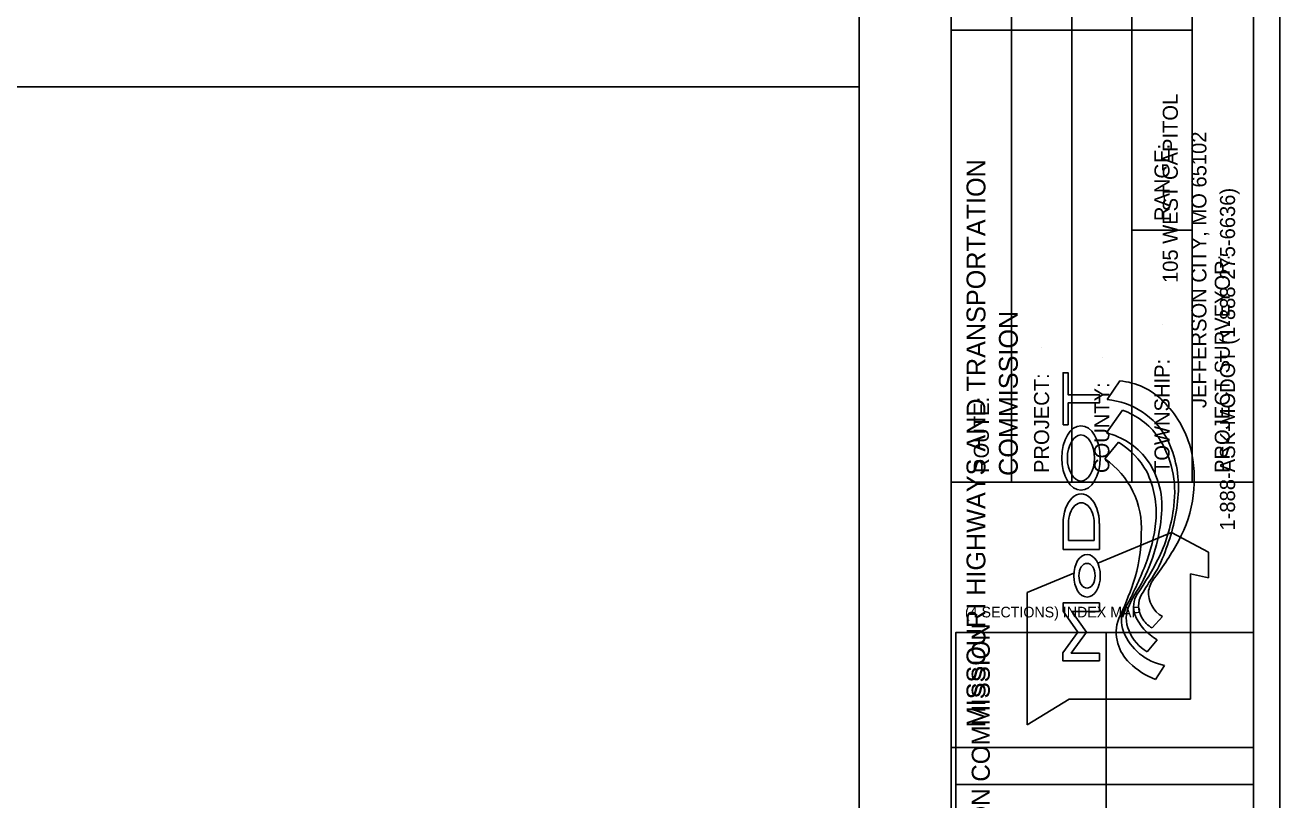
# Model space of a CAD drawing. Extents: x 0 to 31.6, y 0 to 20.8.
# Drawn here: x 23.27 to 31.6, y 5.11 to 10.25 of the extents above; entities that cross this region are included whole.
import ezdxf

# ---------------------------------------------------------------- set-up
doc = ezdxf.new("R2010")
doc.units = 0
for name, color, linetype in [('Border-Border', 7, 'Continuous'), ('Border-Bridge survey map', 7, 'Continuous'), ('Border-Full plan shape', 7, 'Continuous'), ('Border-Full profile shape', 7, 'Continuous'), ('Border-Plan bottom shape', 7, 'Continuous'), ('Border-Plotting block', 7, 'Continuous'), ('Border-Profile bottom shape', 7, 'Continuous'), ('Border-Title block - Final Plans Consultant Manual Seal', 7, 'Continuous'), ('Border-Title block - Final Plans Electronic Seal', 7, 'Continuous'), ('Border-Title block - Location Survey Electronic Seal', 7, 'Continuous'), ('Border-Xsection shape', 7, 'Continuous')]:
    doc.layers.add(name, color=color, linetype=linetype)

msp = doc.modelspace()

# ---------------------------------------------------------------- linework, layer by layer
at = {"layer": 'Border-Border'}
msp.add_line((31.425, 20.5875), (31.425, 0.2125), dxfattribs=at)
at = {"layer": 'Border-Bridge survey map'}
for p, q in [((30.4469, 6.2219), (30.4469, 4.2046)), ((29.4469, 5.2141), (31.4249, 5.2141))]:
    msp.add_line(p, q, dxfattribs=at)
msp.add_lwpolyline([(29.4469, 4.2046), (29.4469, 6.2219), (31.4249, 6.2219)], dxfattribs=at)
at = {"layer": 'Border-Full plan shape'}
msp.add_lwpolyline([(0.8061, 19.9564), (28.8061, 19.9564), (28.8061, 0.8436), (0.8061, 0.8436)], close=True, dxfattribs=at)
at = {"layer": 'Border-Full profile shape'}
msp.add_lwpolyline([(0.8061, 19.9564), (28.8061, 19.9564), (28.8061, 0.8436), (0.8061, 0.8436)], close=True, dxfattribs=at)
at = {"layer": 'Border-Plan bottom shape'}
msp.add_lwpolyline([(0.8061, 10.3253), (28.8061, 10.3253), (28.8061, 0.8436), (0.8061, 0.8436)], close=True, dxfattribs=at)
at = {"layer": 'Border-Plotting block'}
msp.add_lwpolyline([(0, 0), (31.5999, 0), (31.5999, 20.8), (0, 20.8)], close=True, dxfattribs=at)
at = {"layer": 'Border-Profile bottom shape'}
msp.add_lwpolyline([(0.8061, 0.8436), (28.8061, 0.8436), (28.8061, 9.8436), (0.8061, 9.8436)], close=True, dxfattribs=at)
at = {"layer": 'Border-Title block - Final Plans Consultant Manual Seal'}
for p, q in [((29.4171, 20.5875), (29.4171, 0.2125)), ((30.5365, 7.8922), (30.4519, 7.768)), ((30.5541, 7.6979), (30.4483, 7.5468)), ((30.5272, 7.4859), (30.4378, 7.3747)), ((30.16, 6.9464), (30.16, 6.774)), ((30.1963, 6.8334), (30.1963, 6.9464)), ((30.3662, 6.9464), (30.3662, 6.8334)), ((30.4008, 6.774), (30.4008, 6.9464)), ((30.3662, 6.8334), (30.1963, 6.8334)), ((30.8803, 6.8869), (30.3903, 6.6831)), ((31.1267, 6.7566), (30.8803, 6.8869)), ((30.16, 6.774), (30.4008, 6.774)), ((31.1267, 6.5855), (31.1267, 6.7566)), ((30.2315, 6.617), (29.922, 6.4883)), ((31.0071, 5.7793), (31.0071, 6.6109)), ((31.0071, 6.6109), (31.1267, 6.5855)), ((29.922, 6.4883), (29.922, 5.6099)), ((30.7517, 6.2525), (30.821, 6.3285)), ((30.7188, 6.0943), (30.7857, 6.1748)), ((30.7729, 5.9114), (30.8329, 6.0039)), ((29.922, 5.6099), (30.2004, 5.7793)), ((30.2004, 5.7793), (31.0071, 5.7793)), ((29.4171, 5.4599), (31.425, 5.4599))]:
    msp.add_line(p, q, dxfattribs=at)
for points in [[(30.1599, 7.6015), (30.1599, 7.9459), (30.1934, 7.9459), (30.1934, 7.8005), (30.4008, 7.8005), (30.4008, 7.7459), (30.1934, 7.7459), (30.1934, 7.6015)], [(30.4008, 6.0337), (30.1592, 6.0337), (30.1592, 6.0882), (30.2588, 6.2251), (30.16, 6.3638), (30.16, 6.4193), (30.4008, 6.4193), (30.4008, 6.3619), (30.2185, 6.3619), (30.3164, 6.2251), (30.2147, 6.0844), (30.4008, 6.0844)]]:
    msp.add_lwpolyline(points, close=True, dxfattribs=at)
for centre, radius, start, end in [((30.4952, 7.4285), 0.4656, 45.16931, 84.90202), ((30.4076, 7.2631), 0.5069, 28.57249, 84.98895), ((30.3292, 7.2587), 0.7029, 15.82215, 45.3322), ((30.3947, 7.2387), 0.486, 35.48059, 70.84743), ((30.3361, 7.0832), 0.477, 37.82053, 76.39644), ((30.2462, 7.1558), 0.6553, 351.92721, 33.85401), ((30.1918, 7.186), 0.7342, 356.25263, 25.80365), ((30.2447, 7.0264), 0.5393, 29.26655, 58.41911), ((30.1706, 7.2409), 0.8608, 331.45894, 14.08516), ((30.1256, 6.9166), 0.5543, 55.72742, 55.72758), ((30.1256, 6.9166), 0.5543, 356.10332, 55.7272), ((30.2854, 7.0598), 0.5315, 351.87184, 36.46402), ((30.1519, 7.0155), 0.6267, 355.20478, 25.98369), ((29.6592, 7.2299), 1.2685, 339.27778, 355.84654), ((29.8531, 7.1765), 1.048, 334.30971, 353.82369), ((29.6238, 7.1031), 1.1937, 330.80189, 354.30584), ((29.6939, 7.068), 1.0875, 338.33661, 354.46616), ((29.6632, 6.8729), 1.0155, 341.46898, 0.34157), ((30.017, 7.0594), 0.8742, 328.33342, 341.42803), ((29.0087, 7.8983), 2.1957, 323.25469, 330.87553), ((28.6965, 7.4396), 2.1518, 330.82713, 338.94553), ((28.929, 7.6684), 2.0944, 325.33774, 333.14131), ((33.478, 4.796), 3.2616, 146.40943, 149.03928), ((30.9123, 6.4645), 0.1877, 140.18798, 168.85058), ((28.5928, 7.2437), 2.1483, 334.37273, 341.16645), ((31.1325, 6.1801), 0.5778, 143.87617, 156.87144), ((30.9045, 6.4846), 0.177, 174.75269, 241.86614), ((30.7955, 6.3922), 0.167, 149.40426, 197.76384), ((30.8136, 6.3982), 0.1526, 150.25518, 210.64132), ((30.7203, 6.2966), 0.1729, 147.01991, 203.02392), ((30.7795, 6.3173), 0.1996, 153.27349, 205.14999), ((30.9419, 6.465), 0.3295, 202.06293, 241.72012), ((30.7493, 6.2245), 0.2373, 157.70916, 198.17281), ((30.8522, 6.4245), 0.1993, 211.49535, 239.68972), ((30.9032, 6.3653), 0.3681, 201.72885, 258.99607), ((30.8578, 6.3362), 0.279, 201.81038, 240.11136), ((30.7878, 6.2214), 0.2733, 195.0361, 226.99124), ((30.9511, 6.3774), 0.4989, 225.49883, 249.07866)]:
    msp.add_arc(centre, radius, start, end, dxfattribs=at)
for centre, major_axis, ratio in [((30.2788, 7.3805), (0, 0.2144), 0.595517), ((30.2788, 7.3804), (0, -0.153), 0.589579), ((30.3191, 6.5992), (0, 0.1416), 0.623747), ((30.3191, 6.5992), (0, 0.0823), 0.65252)]:
    msp.add_ellipse(centre, major_axis=major_axis, ratio=ratio, dxfattribs=at)
for centre, major_axis, ratio in [((30.2803, 6.9463), (0, -0.1961), 0.614143), ((30.2812, 6.9463), (0, -0.1368), 0.62091)]:
    msp.add_ellipse(centre, major_axis=major_axis, ratio=ratio, start_param=1.570796, end_param=4.712389, dxfattribs=at)
at = {"layer": 'Border-Title block - Final Plans Electronic Seal'}
for p, q in [((29.4171, 20.5875), (29.4171, 0.2125)), ((30.5365, 7.8922), (30.4519, 7.768)), ((30.5541, 7.6979), (30.4483, 7.5468)), ((30.5272, 7.4859), (30.4378, 7.3747)), ((30.16, 6.9464), (30.16, 6.774)), ((30.1963, 6.8334), (30.1963, 6.9464)), ((30.3662, 6.9464), (30.3662, 6.8334)), ((30.4008, 6.774), (30.4008, 6.9464)), ((30.3662, 6.8334), (30.1963, 6.8334)), ((30.8803, 6.8869), (30.3903, 6.6831)), ((31.1267, 6.7566), (30.8803, 6.8869)), ((30.16, 6.774), (30.4008, 6.774)), ((31.1267, 6.5855), (31.1267, 6.7566)), ((30.2315, 6.617), (29.922, 6.4883)), ((31.0071, 5.7793), (31.0071, 6.6109)), ((31.0071, 6.6109), (31.1267, 6.5855)), ((29.922, 6.4883), (29.922, 5.6099)), ((30.7517, 6.2525), (30.821, 6.3285)), ((30.7188, 6.0943), (30.7857, 6.1748)), ((30.7729, 5.9114), (30.8329, 6.0039)), ((29.922, 5.6099), (30.2004, 5.7793)), ((30.2004, 5.7793), (31.0071, 5.7793)), ((29.4171, 5.4599), (31.425, 5.4599))]:
    msp.add_line(p, q, dxfattribs=at)
for points in [[(30.1599, 7.6015), (30.1599, 7.9459), (30.1934, 7.9459), (30.1934, 7.8005), (30.4008, 7.8005), (30.4008, 7.7459), (30.1934, 7.7459), (30.1934, 7.6015)], [(30.4008, 6.0337), (30.1592, 6.0337), (30.1592, 6.0882), (30.2588, 6.2251), (30.16, 6.3638), (30.16, 6.4193), (30.4008, 6.4193), (30.4008, 6.3619), (30.2185, 6.3619), (30.3164, 6.2251), (30.2147, 6.0844), (30.4008, 6.0844)]]:
    msp.add_lwpolyline(points, close=True, dxfattribs=at)
for centre, radius, start, end in [((30.4952, 7.4285), 0.4656, 45.16931, 84.90202), ((30.4076, 7.2631), 0.5069, 28.57249, 84.98895), ((30.3292, 7.2587), 0.7029, 15.82215, 45.3322), ((30.3947, 7.2387), 0.486, 35.48059, 70.84743), ((30.3361, 7.0832), 0.477, 37.82053, 76.39644), ((30.2462, 7.1558), 0.6553, 351.92721, 33.85401), ((30.1918, 7.186), 0.7342, 356.25263, 25.80365), ((30.2447, 7.0264), 0.5393, 29.26655, 58.41911), ((30.1706, 7.2409), 0.8608, 331.45894, 14.08516), ((30.1256, 6.9166), 0.5543, 55.72742, 55.72758), ((30.1256, 6.9166), 0.5543, 356.10332, 55.7272), ((30.2854, 7.0598), 0.5315, 351.87184, 36.46402), ((30.1519, 7.0155), 0.6267, 355.20478, 25.98369), ((29.6592, 7.2299), 1.2685, 339.27778, 355.84654), ((29.8531, 7.1765), 1.048, 334.30971, 353.82369), ((29.6238, 7.1031), 1.1937, 330.80189, 354.30584), ((29.6939, 7.068), 1.0875, 338.33661, 354.46616), ((29.6632, 6.8729), 1.0155, 341.46898, 0.34157), ((30.017, 7.0594), 0.8742, 328.33342, 341.42803), ((29.0087, 7.8983), 2.1957, 323.25469, 330.87553), ((28.6965, 7.4396), 2.1518, 330.82713, 338.94553), ((28.929, 7.6684), 2.0944, 325.33774, 333.14131), ((33.478, 4.796), 3.2616, 146.40943, 149.03928), ((30.9123, 6.4645), 0.1877, 140.18798, 168.85058), ((28.5928, 7.2437), 2.1483, 334.37273, 341.16645), ((31.1325, 6.1801), 0.5778, 143.87617, 156.87144), ((30.9045, 6.4846), 0.177, 174.75269, 241.86614), ((30.7955, 6.3922), 0.167, 149.40426, 197.76384), ((30.8136, 6.3982), 0.1526, 150.25518, 210.64132), ((30.7203, 6.2966), 0.1729, 147.01991, 203.02392), ((30.7795, 6.3173), 0.1996, 153.27349, 205.14999), ((30.9419, 6.465), 0.3295, 202.06293, 241.72012), ((30.7493, 6.2245), 0.2373, 157.70916, 198.17281), ((30.8522, 6.4245), 0.1993, 211.49535, 239.68972), ((30.9032, 6.3653), 0.3681, 201.72885, 258.99607), ((30.8578, 6.3362), 0.279, 201.81038, 240.11136), ((30.7878, 6.2214), 0.2733, 195.0361, 226.99124), ((30.9511, 6.3774), 0.4989, 225.49883, 249.07866)]:
    msp.add_arc(centre, radius, start, end, dxfattribs=at)
for centre, major_axis, ratio in [((30.2788, 7.3805), (0, 0.2144), 0.595517), ((30.2788, 7.3804), (0, -0.153), 0.589579), ((30.3191, 6.5992), (0, 0.1416), 0.623747), ((30.3191, 6.5992), (0, 0.0823), 0.65252)]:
    msp.add_ellipse(centre, major_axis=major_axis, ratio=ratio, dxfattribs=at)
for centre, major_axis, ratio in [((30.2803, 6.9463), (0, -0.1961), 0.614143), ((30.2812, 6.9463), (0, -0.1368), 0.62091)]:
    msp.add_ellipse(centre, major_axis=major_axis, ratio=ratio, start_param=1.570796, end_param=4.712389, dxfattribs=at)
at = {"layer": 'Border-Title block - Location Survey Electronic Seal'}
for p, q in [((29.4171, 20.5875), (29.4171, 0.2125)), ((29.8171, 13.2202), (29.8171, 7.2202)), ((30.2171, 13.2202), (30.2171, 7.2202)), ((30.6171, 13.2202), (30.6171, 7.2202)), ((31.0171, 13.2202), (31.0171, 7.2202)), ((29.4171, 10.2202), (31.0171, 10.2202)), ((30.8117, 9.6142), (30.8117, 9.6142)), ((31.2171, 9.0806), (31.2171, 9.0806)), ((30.6171, 8.8921), (31.0171, 8.8921)), ((30.8171, 8.2648), (30.8171, 8.2648)), ((30.8171, 8.2648), (30.8171, 8.2648)), ((30.0171, 8.115), (30.0171, 8.115)), ((30.4229, 8.0446), (30.4229, 8.0446)), ((29.6171, 7.9411), (29.6171, 7.9411)), ((29.4171, 7.2202), (31.425, 7.2202))]:
    msp.add_line(p, q, dxfattribs=at)
at = {"layer": 'Border-Xsection shape'}
msp.add_lwpolyline([(29.4171, 0.2125), (0.175, 0.2125), (0.175, 20.5875), (29.4171, 20.5875)], close=True, dxfattribs=at)

# ---------------------------------------------------------------- texts
at = {"layer": 'Border-Bridge survey map'}
msp.add_text('(4 SECTIONS) INDEX MAP', height=0.070563, dxfattribs=at).set_placement((29.5084, 6.3227))
at = {"layer": 'Border-Title block - Final Plans Consultant Manual Seal'}
for s, height, p in [('105 WEST CAPITOL', 0.1, (30.922, 8.542)), ('JEFFERSON CITY, MO 65102', 0.1, (31.112, 7.712)), ('MISSOURI HIGHWAYS AND TRANSPORTATION', 0.125, (29.6442, 5.5933)), ('1-888-ASK-MODOT (1-888-275-6636)', 0.1, (31.302, 6.8991)), ('COMMISSION', 0.125, (29.8592, 7.2617))]:
    msp.add_text(s, height=height, rotation=90, dxfattribs=at).set_placement(p)
at = {"layer": 'Border-Title block - Final Plans Electronic Seal'}
for s, height, p in [('105 WEST CAPITOL', 0.1, (30.922, 8.542)), ('JEFFERSON CITY, MO 65102', 0.1, (31.112, 7.712)), ('MISSOURI HIGHWAYS AND TRANSPORTATION', 0.125, (29.6442, 5.5933)), ('1-888-ASK-MODOT (1-888-275-6636)', 0.1, (31.302, 6.8991)), ('COMMISSION', 0.125, (29.8592, 7.2617))]:
    msp.add_text(s, height=height, rotation=90, dxfattribs=at).set_placement(p)
at = {"layer": 'Border-Title block - Location Survey Electronic Seal'}
for s, height, p in [('RANGE:', 0.1, (30.8671, 8.9528)), ('PROJECT SURVEYOR:', 0.1, (31.2671, 7.281)), ('TOWNSHIP:', 0.1, (30.8671, 7.281)), ('PROJECT:', 0.1, (30.0671, 7.281)), ('COUNTY:', 0.1, (30.4671, 7.281)), ('ROUTE:', 0.1, (29.6671, 7.281)), ('SURVEY FOR: MISSOURI HIGHWAYS AND TRANSPORTATION COMMISSION', 0.12, (29.6734, 0.4356))]:
    msp.add_text(s, height=height, rotation=90, dxfattribs=at).set_placement(p)

doc.saveas('drawing.dxf')
